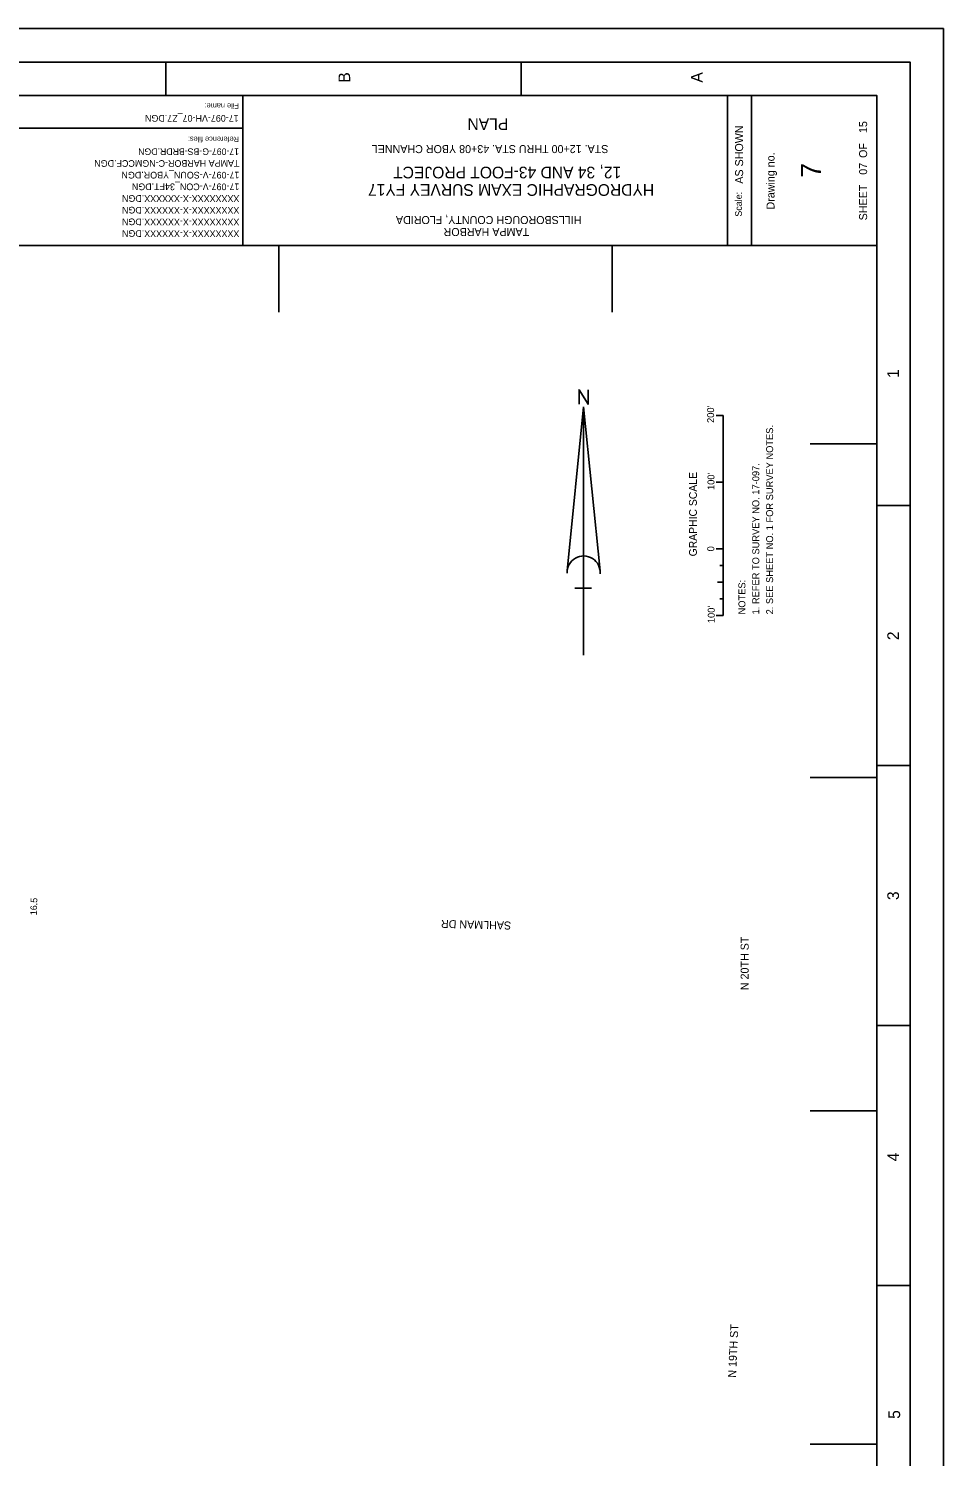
# Model space of a CAD drawing. Extents: x 511597 to 514997, y 1312723 to 1317123.
# Drawn here: x 513625 to 514997, y 1314982 to 1317123 of the extents above; entities that cross this region are included whole.
import ezdxf

# ---------------------------------------------------------------- set-up
doc = ezdxf.new("R2010")
doc.units = 0
for name, color, linetype in [('G-ANNO-NPLT', 7, 'Continuous'), ('G-ANNO-TEXT-DRWG', 7, 'Continuous'), ('G-ANNO-TEXT-PROJ', 7, 'Continuous'), ('G-ANNO-TEXT-TTLB', 7, 'Continuous'), ('G-ANNO-TTLB', 7, 'Continuous'), ('V-ANNO-NOTE', 7, 'Continuous'), ('V-ANNO-SYMB', 7, 'Continuous'), ('V-ROAD-IDEN', 7, 'Continuous'), ('V-TOPO-COOR-STAT', 7, 'Continuous'), ('V-TOPO-SOUN', 7, 'Continuous')]:
    doc.layers.add(name, color=color, linetype=linetype)

msp = doc.modelspace()

# ---------------------------------------------------------------- linework, layer by layer
at = {"layer": 'G-ANNO-NPLT'}
msp.add_lwpolyline([(511596.9, 1312722.8), (511596.9, 1317122.8), (514996.9, 1317122.8), (514996.9, 1312722.8)], close=True, dxfattribs=at)
msp.add_lwpolyline([(514946.9, 1317123), (514996.9, 1317123), (514996.9, 1317073)], dxfattribs=at)
at = {"layer": 'G-ANNO-TTLB'}
for p, q in [((513830.3, 1317072.8), (513830.3, 1317022.8)), ((514363.6, 1317072.8), (514363.6, 1317022.8)), ((513946.1, 1316797.8), (513946.1, 1317022.8)), ((514673.1, 1316797.8), (514673.1, 1317022.8)), ((514708.8, 1316797.8), (514708.8, 1317022.8)), ((513594.7, 1316973.5), (513946.1, 1316973.5)), ((511696.9, 1316797.8), (514896.9, 1316797.8)), ((514946.9, 1316407.8), (514896.9, 1316407.8)), ((514946.9, 1316017.8), (514896.9, 1316017.8)), ((514946.9, 1315627.8), (514896.9, 1315627.8)), ((514946.9, 1315237.8), (514896.9, 1315237.8))]:
    msp.add_line(p, q, dxfattribs=at)
for points in [[(514946.9, 1312772.8), (514946.9, 1317072.8), (511646.9, 1317072.8), (511646.9, 1312772.8)], [(511696.9, 1317022.8), (511696.9, 1312897.8), (514896.9, 1312897.8), (514896.9, 1317022.8)]]:
    msp.add_lwpolyline(points, close=True, dxfattribs=at)
at = {"layer": 'V-ANNO-NOTE'}
for p, q in [((514666.5, 1316542.6), (514656.1, 1316542.6)), ((514666.5, 1316242.6), (514666.5, 1316542.6)), ((514666.5, 1316442.6), (514656.1, 1316442.6)), ((514666.5, 1316342.6), (514656.1, 1316342.6)), ((514666.5, 1316342.6), (514656.1, 1316342.6)), ((514666.5, 1316342.6), (514661.5, 1316342.6)), ((514666.5, 1316317.6), (514661.7, 1316317.6)), ((514666.5, 1316292.6), (514658, 1316292.6)), ((514666.5, 1316267.6), (514661.7, 1316267.6)), ((514666.5, 1316242.6), (514656.1, 1316242.6))]:
    msp.add_line(p, q, dxfattribs=at)
at = {"layer": 'V-ANNO-SYMB'}
for p, q in [((514432.5, 1316309.7), (514457.2, 1316555.5)), ((514457.2, 1316183.1), (514457.2, 1316555.5)), ((514481.9, 1316309.7), (514457.2, 1316555.5)), ((514468.9, 1316283.7), (514444.1, 1316283.7))]:
    msp.add_line(p, q, dxfattribs=at)
msp.add_lwpolyline([(514450.3, 1316559.5), (514450.3, 1316581.2), (514463.8, 1316559.5), (514463.8, 1316581.2)], dxfattribs=at)
msp.add_arc((514457.2, 1316307.2), 24.8, 355.2984, 182.0673, dxfattribs=at)
at = {"layer": 'V-TOPO-COOR-STAT'}
for p, q in [((514000, 1316697.8), (514000, 1316797.8)), ((514500, 1316697.8), (514500, 1316797.8)), ((514896.9, 1316500), (514796.9, 1316500)), ((514896.9, 1316000), (514796.9, 1316000)), ((514896.9, 1315500), (514796.9, 1315500)), ((514896.9, 1315000), (514796.9, 1315000))]:
    msp.add_line(p, q, dxfattribs=at)

# ---------------------------------------------------------------- texts
at = {"layer": 'G-ANNO-TEXT-DRWG'}
for s, height, rotation, p in [('17-097-VH-07_Z7.DGN', 10, 180, (513939.7, 1316993.3)), ('PLAN', 17.5, 180, (514344.1, 1316988.4)), (' 07          15', 12, 90, (514882.4, 1316899.3)), ('STA. 12+00 THRU STA. 43+08 YBOR CHANNEL', 12, 180, (514494.3, 1316948.2)), ('TAMPA HARBOR-C-NGMCCF.DGN', 10, 180, (513940.8, 1316925.6)), ('7', 30, 90, (514813.1, 1316899.2)), ('17-097-V-SOUN_YBOR.DGN', 10, 180, (513940.8, 1316908.1)), ('17-097-V-CON_34FT.DGN', 10, 180, (513940.8, 1316890.6)), ('XXXXXXXX-X-XXXXXX.DGN', 10, 180, (513940.8, 1316873.1)), ('XXXXXXXX-X-XXXXXX.DGN', 10, 180, (513940.8, 1316855.6)), ('XXXXXXXX-X-XXXXXX.DGN', 10, 180, (513940.8, 1316838.1)), ('XXXXXXXX-X-XXXXXX.DGN', 10, 180, (513940.8, 1316820.6))]:
    msp.add_text(s, height=height, rotation=rotation, dxfattribs=at).set_placement(p)
at = {"layer": 'G-ANNO-TEXT-PROJ'}
for s, height, p in [('17-097-G-BS-BRDR.DGN', 9.8, (513940.4, 1316943.2)), ('12, 34 AND 43-FOOT PROJECT', 17.5, (514513.5, 1316915.8)), ('HYDROGRAPHIC EXAM SURVEY FY17', 17.5, (514562.9, 1316889.6)), ('HILLSBOROUGH COUNTY, FLORIDA', 12, (514453.8, 1316841.8)), ('TAMPA HARBOR', 12, (514375.5, 1316823.8))]:
    msp.add_text(s, height=height, rotation=180, dxfattribs=at).set_placement(p)
at = {"layer": 'G-ANNO-TEXT-TTLB'}
for s, height, rotation, p in [('File name:', 8, 180, (513940.1, 1317010.9)), ('Reference files:', 8, 180, (513940.3, 1316960.9)), ('AS SHOWN', 12, 90, (514696.4, 1316890.3)), ('Drawing no.', 12, 90, (514743.5, 1316851.6)), ('SHEET         OF', 12, 90, (514882.4, 1316835.3)), ('Scale:', 10, 90, (514694.5, 1316840.9))]:
    msp.add_text(s, height=height, rotation=rotation, dxfattribs=at).set_placement(p)
at = {"layer": 'G-ANNO-TTLB'}
for s, p in [('B', (514107, 1317041.9)), ('A', (514635.7, 1317041.9)), ('1', (514930.2, 1316598.9)), ('2', (514930.2, 1316205.8)), ('3', (514930.2, 1315816)), ('4', (514930.2, 1315424.2)), ('5', (514931.9, 1315038))]:
    msp.add_text(s, height=17.5, rotation=90, dxfattribs=at).set_placement(p)
at = {"layer": 'V-ANNO-NOTE'}
for s, height, p in [("200'", 10.42, (514652.9, 1316531.5)), ('2. SEE SHEET NO. 1 FOR SURVEY NOTES.', 10.416, (514741.4, 1316244.4)), ('1. REFER TO SURVEY NO. 17-097.', 10.416, (514720.6, 1316244.4)), ('GRAPHIC SCALE', 11.666, (514627, 1316331.4)), ("100'", 10.42, (514653.4, 1316431)), ('0', 10.4, (514653.1, 1316338.9)), ('NOTES:', 10.42, (514699.8, 1316244.4)), ("100'", 10.42, (514653.8, 1316231.3))]:
    msp.add_text(s, height=height, rotation=90, dxfattribs=at).set_placement(p)
at = {"layer": 'V-ROAD-IDEN'}
for s, rotation, p in [('SAHLMAN DR', 178.5586, (514348.5, 1315783.7)), ('N 20TH ST', 90, (514704.7, 1315680.9)), ('N 19TH ST', 87.2295, (514685.6, 1315099.5))]:
    msp.add_text(s, height=12, rotation=rotation, dxfattribs=at).set_placement(p)
at = {"layer": 'V-TOPO-SOUN'}
msp.add_text('16.5 ', height=10, rotation=88.16, dxfattribs=at).set_placement((513637, 1315793.2))

doc.saveas('drawing.dxf')
